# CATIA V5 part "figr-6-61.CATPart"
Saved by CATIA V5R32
Part number: Part1
Bounding box of the stored display mesh (mm): x -50.648 to 50.648, y -72.183 to 72.183, z -40 to 40
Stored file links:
  D:\PROJECTS\Project 2022\CATIA V5 6R 2022\Resources\Part Files\c06_catia_v5_6r2022_prt\figr-6-61.CATPart
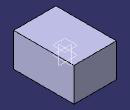
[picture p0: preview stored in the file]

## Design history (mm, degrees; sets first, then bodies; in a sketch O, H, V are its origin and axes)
Set1
  Plane1: type Offset, RefPlane xy-plane, Offset 20
Body1 (main body)
  Sketch1 on xy-plane, origin (0, 0, 0), H (1, 0, 0), V (0, 1, 0)
    line L1 (-50.6478, 72.1832) -> (50.6478, 72.1832)
    line L2 (50.6478, 72.1832) -> (50.6478, -72.1832)
    line L3 (50.6478, -72.1832) -> (-50.6478, -72.1832)
    line L4 (-50.6478, -72.1832) -> (-50.6478, 72.1832)
    axis line L5 (50.6478, -72.1832) -> (-50.6478, 72.1832)
    horizontal: L1 H, L3 H
    vertical: L2 V, L4 V
    midpoint: O L5
  Pad1: profile Sketch1, direction (0, 0, 1), length 40, mirrored extent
